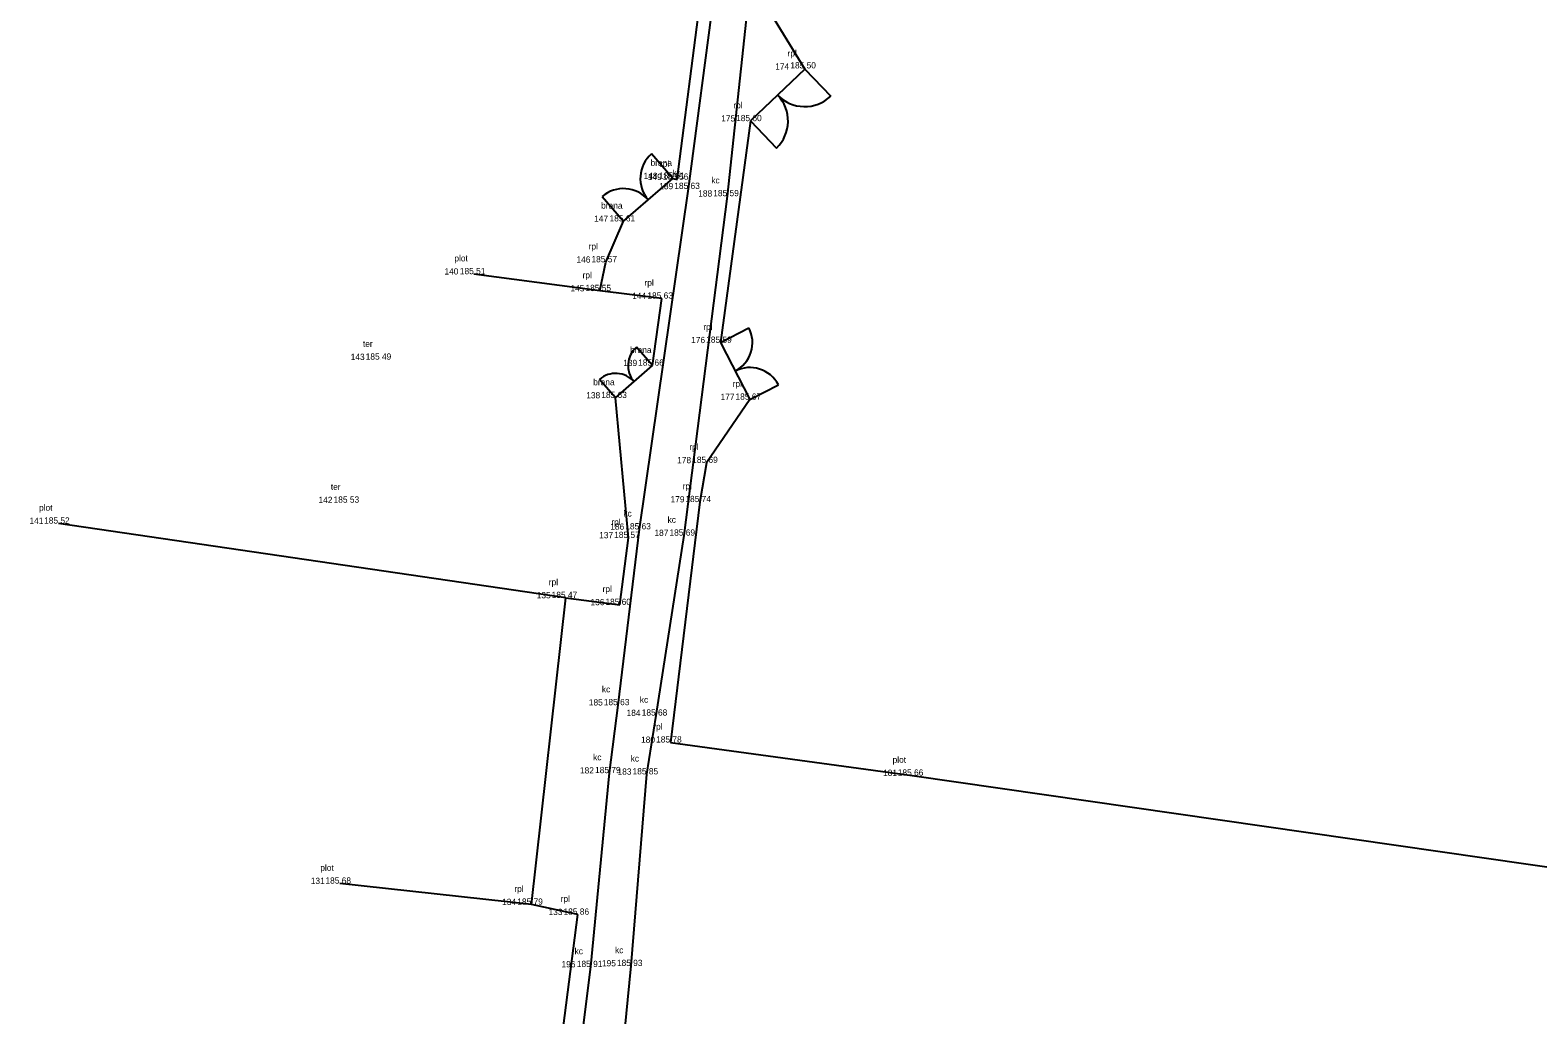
# Model space of a CAD drawing. Extents: x -598527 to -598215, y -1172822 to -1172560.
# Drawn here: x -598389 to -598316.7, y -1172658.9 to -1172611.7 of the extents above; entities that cross this region are included whole.
import ezdxf

# ---------------------------------------------------------------- set-up
doc = ezdxf.new("R2010")
doc.units = 0
for name, color, linetype in [('Body', 7, 'Continuous'), ('Body čísla', 7, 'Continuous'), ('Kody', 7, 'Continuous'), ('PATTERN_CLASS', 7, 'Continuous'), ('Ploty', 7, 'Continuous'), ('Výšky', 7, 'Continuous')]:
    doc.layers.add(name, color=color, linetype=linetype)

msp = doc.modelspace()

# ---------------------------------------------------------------- linework, layer by layer
at = {"layer": 'Body'}
for p, q in [((-598351.84, -1172613.52), (-598351.84, -1172613.52)), ((-598354.44, -1172616.01), (-598354.44, -1172616.01)), ((-598358.16, -1172618.77), (-598358.16, -1172618.77)), ((-598357.96, -1172618.82), (-598357.96, -1172618.82)), ((-598357.41, -1172619.26), (-598357.41, -1172619.26)), ((-598355.54, -1172619.61), (-598355.54, -1172619.61)), ((-598360.53, -1172620.82), (-598360.53, -1172620.82)), ((-598361.38, -1172622.78), (-598361.38, -1172622.78)), ((-598367.71, -1172623.35), (-598367.71, -1172623.35)), ((-598361.67, -1172624.16), (-598361.67, -1172624.16)), ((-598358.7, -1172624.52), (-598358.7, -1172624.52)), ((-598355.88, -1172626.64), (-598355.88, -1172626.64)), ((-598372.21, -1172627.45), (-598372.21, -1172627.45)), ((-598359.14, -1172627.74), (-598359.14, -1172627.74)), ((-598360.91, -1172629.29), (-598360.91, -1172629.29)), ((-598354.47, -1172629.37), (-598354.47, -1172629.37)), ((-598356.55, -1172632.4), (-598356.55, -1172632.4)), ((-598373.75, -1172634.31), (-598373.75, -1172634.31)), ((-598356.87, -1172634.28), (-598356.87, -1172634.28)), ((-598387.63, -1172635.31), (-598387.63, -1172635.31)), ((-598359.76, -1172635.59), (-598359.76, -1172635.59)), ((-598357.64, -1172635.89), (-598357.64, -1172635.89)), ((-598360.29, -1172636), (-598360.29, -1172636)), ((-598363.29, -1172638.88), (-598363.29, -1172638.88)), ((-598360.71, -1172639.21), (-598360.71, -1172639.21)), ((-598360.79, -1172644.02), (-598360.79, -1172644.02)), ((-598358.97, -1172644.52), (-598358.97, -1172644.52)), ((-598358.28, -1172645.81), (-598358.28, -1172645.81)), ((-598361.21, -1172647.28), (-598361.21, -1172647.28)), ((-598359.41, -1172647.34), (-598359.41, -1172647.34)), ((-598346.69, -1172647.4), (-598346.69, -1172647.4)), ((-598374.14, -1172652.58), (-598374.14, -1172652.58)), ((-598364.94, -1172653.59), (-598364.94, -1172653.59)), ((-598362.72, -1172654.07), (-598362.72, -1172654.07)), ((-598362.1, -1172656.58), (-598362.1, -1172656.58)), ((-598360.16, -1172656.53), (-598360.16, -1172656.53))]:
    msp.add_line(p, q, dxfattribs=at)
at = {"layer": 'PATTERN_CLASS'}
for points in [[(-598364.75, -1172697.57), (-598364.74, -1172694.18), (-598362.94, -1172680.98), (-598361.75, -1172670.91), (-598361.46, -1172669.75), (-598360.16, -1172656.53), (-598359.41, -1172647.34), (-598358.97, -1172644.52), (-598357.622, -1172635.884), (-598355.54, -1172619.61), (-598354.53, -1172610.23), (-598352.51, -1172595.34), (-598351.22, -1172585.21), (-598348.76, -1172585.57), (-598347.59, -1172581.3), (-598346.856, -1172579.801), (-598345.8, -1172578.12), (-598344.503, -1172576.902), (-598343.57, -1172576.22)], [(-598367.73, -1172694.27), (-598365.54, -1172680.7), (-598365.43, -1172680.27), (-598363.79, -1172670.22), (-598363.69, -1172669.33), (-598362.1, -1172656.58), (-598361.21, -1172647.28), (-598360.79, -1172644.02), (-598359.76, -1172635.59), (-598357.41, -1172619.26), (-598356.18, -1172609.95), (-598354.7, -1172595.04), (-598353.57, -1172584.71)]]:
    msp.add_lwpolyline(points, dxfattribs=at)
at = {"layer": 'Ploty'}
for p, q in [((-598357.96, -1172618.82), (-598356.8, -1172609.81)), ((-598353.73, -1172610.43), (-598351.84, -1172613.52)), ((-598351.84, -1172613.52), (-598354.44, -1172616.01)), ((-598351.84, -1172613.52), (-598350.595, -1172614.82)), ((-598354.44, -1172616.01), (-598355.88, -1172626.64)), ((-598354.44, -1172616.01), (-598353.195, -1172617.31)), ((-598358.16, -1172618.77), (-598359.185, -1172617.585)), ((-598360.53, -1172620.82), (-598358.16, -1172618.77)), ((-598358.16, -1172618.77), (-598357.96, -1172618.82)), ((-598361.555, -1172619.635), (-598360.53, -1172620.82)), ((-598361.38, -1172622.78), (-598360.53, -1172620.82)), ((-598361.67, -1172624.16), (-598361.38, -1172622.78)), ((-598361.67, -1172624.16), (-598367.71, -1172623.35)), ((-598358.7, -1172624.52), (-598361.67, -1172624.16)), ((-598359.14, -1172627.74), (-598358.7, -1172624.52)), ((-598355.88, -1172626.64), (-598354.515, -1172625.935)), ((-598359.14, -1172627.74), (-598359.915, -1172626.855)), ((-598355.88, -1172626.64), (-598354.47, -1172629.37)), ((-598360.91, -1172629.29), (-598359.14, -1172627.74)), ((-598360.91, -1172629.29), (-598361.685, -1172628.405)), ((-598354.47, -1172629.37), (-598353.105, -1172628.665)), ((-598360.29, -1172636), (-598360.91, -1172629.29)), ((-598354.47, -1172629.37), (-598356.55, -1172632.4)), ((-598356.55, -1172632.4), (-598356.87, -1172634.28)), ((-598356.87, -1172634.28), (-598358.28, -1172645.81)), ((-598363.29, -1172638.88), (-598387.63, -1172635.31)), ((-598360.71, -1172639.21), (-598360.29, -1172636)), ((-598364.94, -1172653.59), (-598363.29, -1172638.88)), ((-598363.29, -1172638.88), (-598360.71, -1172639.21)), ((-598358.28, -1172645.81), (-598346.69, -1172647.4)), ((-598346.69, -1172647.4), (-598277.44, -1172657.38)), ((-598364.94, -1172653.59), (-598374.14, -1172652.58)), ((-598362.72, -1172654.07), (-598364.94, -1172653.59)), ((-598364.62, -1172668.75), (-598362.72, -1172654.07))]:
    msp.add_line(p, q, dxfattribs=at)
for centre, radius, start, end in [((-598354.44, -1172616.01), 1.8, 313.76197, 43.76197), ((-598351.84, -1172613.52), 1.8, 223.76197, 313.76197), ((-598358.16, -1172618.77), 1.567, 130.85911, 220.85911), ((-598360.53, -1172620.82), 1.567, 40.85911, 130.85911), ((-598355.88, -1172626.64), 1.536, 297.31561, 27.31561), ((-598359.14, -1172627.74), 1.176, 131.20883, 221.20883), ((-598354.47, -1172629.37), 1.536, 27.31561, 117.31561), ((-598360.91, -1172629.29), 1.176, 41.20883, 131.20883)]:
    msp.add_arc(centre, radius, start, end, dxfattribs=at)

# ---------------------------------------------------------------- texts
at = {"layer": 'Body čísla'}
for s, p in [('174', (-598353.254, -1172613.543)), ('175', (-598355.845, -1172616.033)), ('148', (-598359.568, -1172618.793)), ('149', (-598359.366, -1172618.843)), ('189', (-598358.816, -1172619.283)), ('188', (-598356.948, -1172619.633)), ('147', (-598361.938, -1172620.843)), ('146', (-598362.787, -1172622.803)), ('140', (-598369.12, -1172623.373)), ('145', (-598363.075, -1172624.183)), ('144', (-598360.114, -1172624.543)), ('176', (-598357.287, -1172626.663)), ('143', (-598373.617, -1172627.473)), ('139', (-598360.546, -1172627.763)), ('138', (-598362.318, -1172629.313)), ('177', (-598355.878, -1172629.393)), ('178', (-598357.958, -1172632.423)), ('142', (-598375.161, -1172634.333)), ('179', (-598358.276, -1172634.303)), ('141', (-598389.021, -1172635.333)), ('137', (-598361.698, -1172636.023)), ('186', (-598361.167, -1172635.613)), ('187', (-598359.048, -1172635.913)), ('135', (-598364.695, -1172638.903)), ('136', (-598362.117, -1172639.233)), ('185', (-598362.195, -1172644.043)), ('184', (-598360.384, -1172644.543)), ('180', (-598359.69, -1172645.833)), ('182', (-598362.621, -1172647.303)), ('183', (-598360.817, -1172647.363)), ('181', (-598348.081, -1172647.423)), ('131', (-598375.531, -1172652.603)), ('134', (-598366.354, -1172653.613)), ('133', (-598364.127, -1172654.093)), ('196', (-598363.507, -1172656.603)), ('195', (-598361.565, -1172656.553))]:
    msp.add_text(s, height=0.3, dxfattribs=at).set_placement(p)
at = {"layer": 'Kody'}
for s, p in [('rpl', (-598352.666, -1172612.913)), ('rpl', (-598355.266, -1172615.403)), ('brana', (-598359.235, -1172618.163)), ('rpl', (-598358.786, -1172618.213)), ('kc', (-598358.188, -1172618.653)), ('kc', (-598356.318, -1172619.003)), ('brana', (-598361.605, -1172620.213)), ('rpl', (-598362.206, -1172622.173)), ('plot', (-598368.645, -1172622.743)), ('rpl', (-598362.496, -1172623.553)), ('rpl', (-598359.526, -1172623.913)), ('rpl', (-598356.706, -1172626.033)), ('ter', (-598373.029, -1172626.843)), ('brana', (-598360.215, -1172627.133)), ('brana', (-598361.985, -1172628.683)), ('rpl', (-598355.296, -1172628.763)), ('rpl', (-598357.376, -1172631.793)), ('ter', (-598374.569, -1172633.703)), ('rpl', (-598357.696, -1172633.673)), ('plot', (-598388.565, -1172634.703)), ('rpl', (-598361.116, -1172635.393)), ('kc', (-598360.538, -1172634.983)), ('kc', (-598358.418, -1172635.283)), ('rpl', (-598364.116, -1172638.273)), ('rpl', (-598361.536, -1172638.603)), ('kc', (-598361.568, -1172643.413)), ('kc', (-598359.748, -1172643.913)), ('rpl', (-598359.106, -1172645.203)), ('kc', (-598361.988, -1172646.673)), ('kc', (-598360.188, -1172646.733)), ('plot', (-598347.625, -1172646.793)), ('plot', (-598375.075, -1172651.973)), ('rpl', (-598365.766, -1172652.983)), ('rpl', (-598363.546, -1172653.463)), ('kc', (-598362.878, -1172655.973)), ('kc', (-598360.938, -1172655.923))]:
    msp.add_text(s, height=0.3, dxfattribs=at).set_placement(p)
at = {"layer": 'Výšky'}
for s, p in [('185 50', (-598352.53, -1172613.489)), ('185 60', (-598355.13, -1172616.018)), ('185 61', (-598358.831, -1172618.778)), ('185 56', (-598358.648, -1172618.828)), ('185 63', (-598358.097, -1172619.268)), ('185 59', (-598356.227, -1172619.618)), ('185 61', (-598361.201, -1172620.828)), ('185 57', (-598362.069, -1172622.788)), ('185 51', (-598368.381, -1172623.358)), ('185 55', (-598362.356, -1172624.168)), ('185 63', (-598359.387, -1172624.528)), ('185 59', (-598356.567, -1172626.648)), ('185 49', (-598372.897, -1172627.458)), ('185 66', (-598359.828, -1172627.748)), ('185 63', (-598361.597, -1172629.298)), ('185 67', (-598355.159, -1172629.378)), ('185 69', (-598357.237, -1172632.408)), ('185 53', (-598374.437, -1172634.318)), ('185 74', (-598357.564, -1172634.288)), ('185 52', (-598388.321, -1172635.318)), ('185 57', (-598360.979, -1172636.008)), ('185 63', (-598360.447, -1172635.598)), ('185 69', (-598358.327, -1172635.898)), ('185 47', (-598363.979, -1172638.888)), ('185 60', (-598361.4, -1172639.218)), ('185 63', (-598361.477, -1172644.028)), ('185 68', (-598359.658, -1172644.528)), ('185 78', (-598358.968, -1172645.818)), ('185 79', (-598361.897, -1172647.288)), ('185 85', (-598360.096, -1172647.348)), ('185 66', (-598347.378, -1172647.408)), ('185 68', (-598374.828, -1172652.588)), ('185 79', (-598365.627, -1172653.598)), ('185 86', (-598363.408, -1172654.078)), ('185 91', (-598362.771, -1172656.588)), ('185 93', (-598360.847, -1172656.538))]:
    msp.add_text(s, height=0.3, dxfattribs=at).set_placement(p)

doc.saveas('drawing.dxf')
